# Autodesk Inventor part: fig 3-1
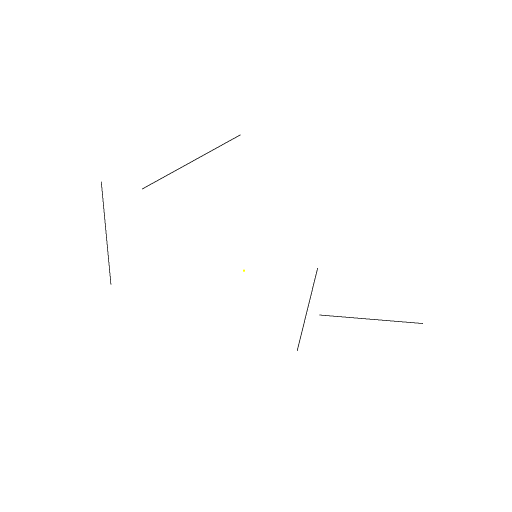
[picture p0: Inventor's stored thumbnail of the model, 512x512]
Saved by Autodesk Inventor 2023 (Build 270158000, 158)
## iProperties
Created: 2011-07
Part Number: fig 3-1
Material: Generic
Document SubType Name: Modeling
Designer: CadCim
Density: 1 g/cm^3
Appearance: Default
Author: CadCim
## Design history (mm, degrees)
sketch "Sketch1"
  geometry: L1 (-24.535, 0.895)-(-9.053, -12.994); L2 (-20.147, 3.302)-(-19.785, 19.15); L3 (5.706, 6.44)-(15.874, -7.118); L4 (12.565, -0.112)-(22.33, 7.212); 1 further point
  constraints: 8 end point, 1 perpendicular, 1 other
